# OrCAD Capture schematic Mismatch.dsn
size A
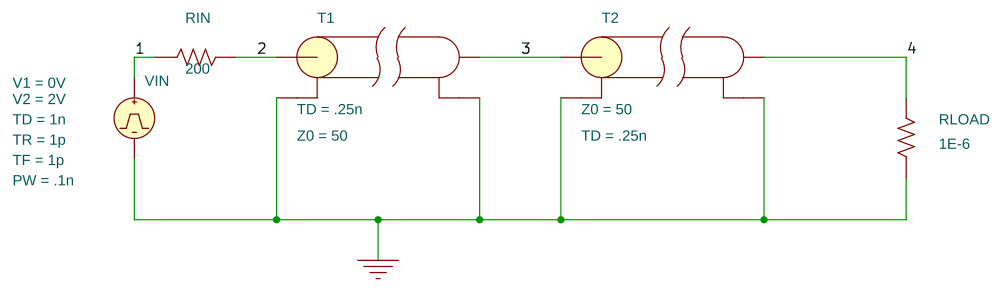
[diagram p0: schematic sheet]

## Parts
RIN  200  [AX/RC05]
RLOAD  1E-6  [AX/RC05]
T1  T
T2  T
VIN  VPULSE

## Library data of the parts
RIN RLOAD = R
T1 T2 = T: TD: .25n; Z0: 50
VIN = VPULSE: PW: .1n; TD: 1n; TF: 1p; TR: 1p; V1: 0V; V2: 2V

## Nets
0: RLOAD.1 T1.2(A-) T1.4(B-) T2.2(A-) T2.4(B-) VIN.2(-)
1: RIN.1 VIN.1(+)
2: RIN.2 T1.1(A+)
3: T1.3(B+) T2.1(A+)
4: RLOAD.2 T2.3(B+)
